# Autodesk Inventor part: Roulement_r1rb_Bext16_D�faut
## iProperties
Created: 2011-01
Part Number: Roulement_r1rb_Bext16_D�faut
Document SubType Name: Modeling
Designer: eric
Density: 1 g/cm^3
Mass: 0.82877 g
Surface Area: 11.5266 cm^2
Volume: 0.82877 cm^3
Author: eric
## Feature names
1. Base1
